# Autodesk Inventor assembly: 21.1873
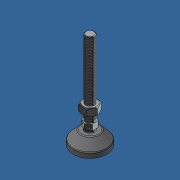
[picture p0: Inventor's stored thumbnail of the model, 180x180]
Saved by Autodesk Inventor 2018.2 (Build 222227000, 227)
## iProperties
Created: 2007-03
Part Number: 21.1873
Document SubType Name: Assembly
Designer: Andy Moles
Description: LEVELING FOOT M12 45mm BASE
Author: Andy Moles
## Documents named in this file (5)
- Y:\INVENTOR LIBRARIES\PARTS LIBRARY\FEET WHEELS FLOOR FASTENING SUPPORTS\21.1873 LEVELING FOOT M12 45mm BASE.iam
- Y:\INVENTOR LIBRARIES\PARTS LIBRARY\FEET WHEELS FLOOR FASTENING SUPPORTS\SUBCOMPONENTS\LEVELING FEET SUBCOMPONENTS\PAD 45mm PLASTIC.ipt
- Y:\INVENTOR LIBRARIES\PARTS LIBRARY\FEET WHEELS FLOOR FASTENING SUPPORTS\SUBCOMPONENTS\LEVELING FEET SUBCOMPONENTS\ANTI-SKID PAD 45mm.ipt
- Y:\INVENTOR LIBRARIES\PARTS LIBRARY\FASTENING ELEMENTS\NUTS\21.1528 M12 HEX NUT.ipt
- Y:\INVENTOR LIBRARIES\PARTS LIBRARY\FEET WHEELS FLOOR FASTENING SUPPORTS\SUBCOMPONENTS\LEVELING FEET SUBCOMPONENTS\THREADED STUD 12mm 100mm THREAD.ipt
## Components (4 placed, 4 different names)
1. ANTI-SKID PAD 45mm:1 — Insert:1
2. PAD 45mm PLASTIC:1 — Insert:1, Tangent:1, Mate:1
3. THREADED STUD 12mm 100mm THREAD:1 — Tangent:1, Mate:1, Mate:2
4. 21.1528 M12 HEX NUT:1 — Mate:2
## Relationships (4: Mate 2, Insert 1, Tangent 1)
- Insert:1: ANTI-SKID PAD 45mm:1 ↔ PAD 45mm PLASTIC:1
- Tangent:1: PAD 45mm PLASTIC:1 ↔ THREADED STUD 12mm 100mm THREAD:1
- Mate:1: PAD 45mm PLASTIC:1 ↔ THREADED STUD 12mm 100mm THREAD:1
- Mate:2: THREADED STUD 12mm 100mm THREAD:1 ↔ 21.1528 M12 HEX NUT:1
